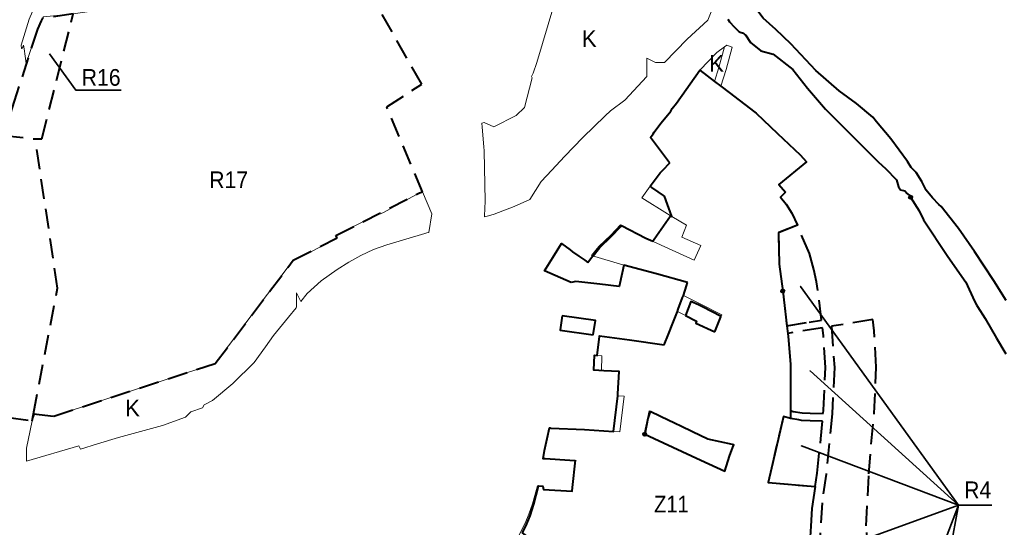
# Model space of a CAD drawing. Extents: x -650276 to -642489, y -1074311 to -1066658.
# Drawn here: x -646603 to -645192, y -1069923 to -1069193 of the extents above; entities that cross this region are included whole.
import ezdxf

# ---------------------------------------------------------------- set-up
doc = ezdxf.new("R2010")
doc.units = 0
doc.header["$LTSCALE"] = 9.6
doc.header["$PDMODE"] = 32
doc.header["$PDSIZE"] = 4.8
doc.linetypes.add('MEDIUM_DASHED', pattern=[4.5, 3, -1.5])
for name, color, linetype, lineweight in [('44', 7, 'Continuous', 40), ('45', 7, 'Continuous', 40), ('47', 7, 'Continuous', 13), ('48', 7, 'Continuous', 13), ('61', 7, 'MEDIUM_DASHED', 40), ('62', 7, 'Continuous', 35), ('63', 7, 'Continuous', 13)]:
    doc.layers.add(name, color=color, linetype=linetype, lineweight=lineweight)

msp = doc.modelspace()

# ---------------------------------------------------------------- linework, layer by layer
at = {"layer": '44'}
for points in [[(-645184.88, -1069596.58), (-645202.56, -1069568.23), (-645230.1, -1069525.98), (-645253.4, -1069493.06), (-645278.31, -1069461.33), (-645281.4, -1069458.4), (-645290.5, -1069449.03), (-645299.61, -1069437.97), (-645306.16, -1069425.55), (-645314.14, -1069412.54), (-645321.1, -1069405.21), (-645326.59, -1069396.64), (-645350.63, -1069363.98), (-645371.12, -1069339.47), (-645376.38, -1069332.65), (-645400.07, -1069313.32), (-645424.8, -1069295.24), (-645458.45, -1069265.56), (-645494.13, -1069227.63), (-645515.89, -1069206.66), (-645534.25, -1069190.56), (-645543.43, -1069178.39)], [(-645584.73, -1069191.88), (-645582.63, -1069195.88), (-645575.58, -1069203.57), (-645568.9, -1069209.87), (-645567.07, -1069210.45), (-645562.17, -1069212.02), (-645560.72, -1069214.25), (-645559.33, -1069214.54), (-645552.2, -1069225.59), (-645537.44, -1069237.41), (-645519.59, -1069242.38), (-645491.63, -1069264.25), (-645470.44, -1069291.24), (-645444.62, -1069321.35), (-645405.7, -1069360.27), (-645368.13, -1069397.37), (-645358.04, -1069406.84), (-645342.49, -1069423.06), (-645339.31, -1069433.27), (-645336.66, -1069437.47), (-645330.57, -1069438.89), (-645327.2, -1069442.53), (-645323.36, -1069445.79), (-645322.13, -1069447.96)], [(-645322.13, -1069447.96), (-645309.62, -1069467.79), (-645303.57, -1069480.49), (-645268.57, -1069533.23), (-645242.75, -1069570.26), (-645230.42, -1069597.39), (-645227.27, -1069602.68), (-645225.7, -1069605.32), (-645214.76, -1069622.37), (-645198.41, -1069650.49), (-645185.17, -1069673.38)]]:
    msp.add_lwpolyline(points, dxfattribs=at)
msp.add_point((-645322.13, -1069447.96), dxfattribs=at)
at = {"layer": '45'}
msp.add_line((-645704.355, -1069788.786), (-645623.75, -1069825.97), dxfattribs=at)
for points in [[(-645668.722, -1069398.75), (-645696.19, -1069362.01), (-645692.38, -1069356.67), (-645690.81, -1069354.28), (-645687.22, -1069349), (-645680.8, -1069341.08), (-645667, -1069324.06), (-645664.89, -1069320.2), (-645658.9, -1069312.83), (-645625.11, -1069265.42), (-645604.114, -1069281.49), (-645594.94, -1069288.511)], [(-645594.94, -1069288.511), (-645583.13, -1069297.55), (-645546.19, -1069325.81), (-645544.26, -1069327.35), (-645513.41, -1069356.18), (-645480.72, -1069386.96), (-645471.738, -1069397.026), (-645511.464, -1069429.794), (-645501.878, -1069440.838)], [(-645675.91, -1069446.56), (-645694.21, -1069433.78), (-645696.45, -1069432.21), (-645682.28, -1069412.88), (-645678.06, -1069408.54), (-645668.61, -1069398.9), (-645668.722, -1069398.75)], [(-645501.878, -1069440.838), (-645508.994, -1069447.955), (-645501, -1069458), (-645493, -1069471), (-645484.783, -1069488.256), (-645512, -1069499), (-645511, -1069544), (-645506, -1069583)], [(-645786.388, -1069541.673), (-645779.376, -1069532.962), (-645778.754, -1069532.198), (-645769.369, -1069520.672), (-645768.995, -1069520.305), (-645752.715, -1069504.328), (-645738.986, -1069489.868), (-645737.897, -1069488.534), (-645702.82, -1069506.64), (-645692.87, -1069511.229), (-645690.84, -1069508.32), (-645667.31, -1069474.6), (-645665.58, -1069475.61), (-645675.91, -1069446.56)], [(-645836.44, -1069534.5), (-645824.05, -1069514.34), (-645811.75, -1069523.81), (-645808.1, -1069526.61), (-645799.07, -1069532.8), (-645790.62, -1069538.59), (-645786.388, -1069541.673)], [(-645810.08, -1069570.39), (-645848.78, -1069553.91), (-645836.44, -1069534.5)], [(-645643.16, -1069570.6), (-645687.29, -1069558.04), (-645734.5, -1069545.89), (-645736.8, -1069556.91), (-645741.14, -1069576.19), (-645769.04, -1069573), (-645803.513, -1069569.263), (-645810.08, -1069570.39)], [(-645676.34, -1069660.28), (-645670.23, -1069644.67), (-645664.19, -1069629.24), (-645657.52, -1069612.2), (-645656.15, -1069608.71), (-645649.91, -1069592.39), (-645648.68, -1069589.06), (-645644.56, -1069575.61), (-645643.16, -1069570.6)], [(-645506, -1069583), (-645500.137, -1069632.833), (-645500.137, -1069632.833)], [(-645594.58, -1069619.56), (-645621.56, -1069605.68), (-645626.95, -1069602.91), (-645638.203, -1069597.8), (-645645.715, -1069618.085)], [(-645823.082, -1069618.279), (-645823.13, -1069618.452), (-645825.295, -1069632.053), (-645826.133, -1069638.843), (-645826.151, -1069639.057), (-645778.45, -1069645.92)], [(-645823.082, -1069618.279), (-645823.13, -1069618.452), (-645825.295, -1069632.053), (-645826.133, -1069638.843), (-645826.151, -1069639.057), (-645778.45, -1069645.92)], [(-645778.45, -1069645.92), (-645775.46, -1069625.13), (-645823.082, -1069618.279)], [(-645778.45, -1069645.92), (-645775.46, -1069625.13), (-645823.082, -1069618.279)], [(-645645.715, -1069618.085), (-645629.78, -1069626.03), (-645630.93, -1069628.84), (-645603.7, -1069641.75)], [(-645603.7, -1069641.75), (-645594.818, -1069620.139), (-645594.58, -1069619.56)], [(-645500.137, -1069632.833), (-645498, -1069648), (-645495, -1069688), (-645495, -1069744), (-645495, -1069766), (-645504.976, -1069763.332), (-645527, -1069858), (-645459.312, -1069864.01), (-645464.288, -1069895.362), (-645465.756, -1069921.035), (-645469.701, -1069990.011)], [(-645839.721, -1069780.247), (-645839.658, -1069779.835), (-645791.2, -1069781.92), (-645749.48, -1069784.61), (-645743.36, -1069733.7), (-645743.01, -1069730.72), (-645741.43, -1069698.68), (-645763.24, -1069697.58), (-645777.62, -1069696.85), (-645776.45, -1069675.26), (-645773.02, -1069675.47), (-645769.36, -1069648), (-645769.264, -1069647.213), (-645726.57, -1069653.22), (-645676.34, -1069660.28)], [(-645696.517, -1069756.039), (-645700.028, -1069766.286), (-645704.355, -1069788.786)], [(-645660.57, -1069773.31), (-645681.76, -1069763.13), (-645696.517, -1069756.039)], [(-645804.185, -1069825.84), (-645804.28, -1069826.76), (-645812.18, -1069826.3), (-645847.62, -1069824.26), (-645850.63, -1069824.09), (-645848.35, -1069812.09), (-645844.57, -1069795.07), (-645841.41, -1069779.76), (-645839.658, -1069779.835), (-645839.721, -1069780.247)], [(-645613.84, -1069795.78), (-645635.79, -1069785.23), (-645652.378, -1069777.251), (-645660.57, -1069773.31)], [(-645623.75, -1069825.97), (-645589.23, -1069841.89), (-645582.31, -1069820.05), (-645577.52, -1069807.26), (-645576.34, -1069804.13), (-645578.134, -1069803.731), (-645613.84, -1069795.78)], [(-645742.967, -1069941.862), (-645768.424, -1069948.431), (-645833, -1069966), (-645880.431, -1069930.3), (-645874.219, -1069917.496), (-645869.262, -1069905.935), (-645863.95, -1069889.468), (-645857.289, -1069863.338), (-645857.204, -1069862.954), (-645850.92, -1069863.41), (-645849.79, -1069868.4), (-645808.84, -1069870.75), (-645808.28, -1069865.39), (-645804.185, -1069825.84)]]:
    msp.add_lwpolyline(points, dxfattribs=at)
for p in [(-645506, -1069583), (-645704.355, -1069788.786)]:
    msp.add_point(p, dxfattribs=at)
at = {"layer": '47'}
for points in [[(-646593.793, -1069255.911), (-646577.878, -1069206.485), (-646572.586, -1069194.485), (-646569.114, -1069188.86), (-646526.31, -1069184.381), (-646479.84, -1069177.626), (-646250.409, -1069137.52), (-646153.307, -1069059.947), (-646161.484, -1069046.228), (-646256.824, -1069123.414)], [(-646547.412, -1069071.71), (-646549.91, -1069072.542), (-646564.54, -1069125.08), (-646564.605, -1069125.271), (-646574.978, -1069163.017), (-646574.978, -1069163.017), (-646574.33, -1069162.04), (-646575.87, -1069164.54), (-646581.29, -1069173.32), (-646589.56, -1069192.07), (-646601.41, -1069229.34)], [(-645835.157, -1069172.184), (-645859.43, -1069254.08), (-645864.96, -1069269.78), (-645867.42, -1069274.21), (-645866.45, -1069276.32), (-645877.15, -1069319.06), (-645877.15, -1069319.06), (-645889.29, -1069330.52), (-645921.56, -1069346.6), (-645935.33, -1069340.64), (-645938.89, -1069341.56), (-645938.399, -1069347.452)], [(-645938.399, -1069347.452), (-645936.046, -1069375.651), (-645935.58, -1069381.24), (-645933.97, -1069453.52), (-645934.8, -1069474.71), (-645935.05, -1069476.32), (-645928.99, -1069474.55), (-645921.13, -1069472.25), (-645892.03, -1069461.43), (-645869.91, -1069451.02), (-645853.28, -1069425.27), (-645838.17, -1069409.28), (-645819.62, -1069389.66), (-645793.63, -1069362.15), (-645761.411, -1069331.17), (-645753.58, -1069323.64), (-645733.1, -1069308.58), (-645701.62, -1069274.36), (-645701.33, -1069247.86), (-645689, -1069254.5), (-645675.82, -1069254.48), (-645643.34, -1069220.59), (-645613.9, -1069193.45), (-645608.71, -1069181.51)], [(-646601.41, -1069229.34), (-646600.68, -1069234.21), (-646599.79, -1069234.07), (-646597.77, -1069229.37), (-646596.95, -1069234.83), (-646593.793, -1069255.911)], [(-645604.114, -1069281.49), (-645597.738, -1069261.522), (-645589.844, -1069231.908), (-645600.55, -1069239.93), (-645625.11, -1069265.42)], [(-645625.11, -1069265.42), (-645625.11, -1069265.42), (-645604.114, -1069281.49)], [(-646023.96, -1069440.34), (-646028.16, -1069441.58), (-646080.35, -1069469.89), (-646102.15, -1069479.49), (-646148.5, -1069503), (-646146.8, -1069506.6), (-646189.17, -1069528.74), (-646209.9, -1069538.5), (-646321.973, -1069686.855), (-646554.262, -1069762.602), (-646581.489, -1069759.421), (-646585.51, -1069769.57)], [(-646017.63, -1069499.08), (-646017.63, -1069499.08), (-646015.16, -1069498.74), (-646010.65, -1069471.91), (-646023.96, -1069440.34)], [(-646491.18, -1069802.78), (-646491.18, -1069802.78), (-646460.97, -1069793.56), (-646397.74, -1069776.29), (-646364.67, -1069764.23), (-646357, -1069756.7), (-646340.48, -1069750.92), (-646337.97, -1069746.4), (-646325.92, -1069740.05), (-646296.64, -1069715.72), (-646266.27, -1069685.75), (-646250, -1069663.09), (-646238.19, -1069646.63), (-646212.43, -1069615.33), (-646210.03, -1069612.42), (-646205.9, -1069607.17), (-646205, -1069606.03), (-646205.25, -1069585.67), (-646198.82, -1069597.83), (-646190.07, -1069586.48), (-646169.9, -1069568.04), (-646146.81, -1069551.97), (-646129.87, -1069541.19), (-646112.56, -1069531.78), (-646094.39, -1069523.34), (-646075.48, -1069516.38), (-646020.75, -1069500), (-646017.63, -1069499.08)], [(-646585.51, -1069769.57), (-646588.25, -1069783.37), (-646593.34, -1069808.99), (-646593.34, -1069827.68)], [(-646593.34, -1069827.68), (-646518.19, -1069805.27), (-646515.63, -1069810.24), (-646491.18, -1069802.78)]]:
    msp.add_lwpolyline(points, dxfattribs=at)
at = {"layer": '61'}
for points in [[(-646583.457, -1069759.191), (-646554.262, -1069762.602), (-646321.973, -1069686.855), (-646209.9, -1069538.5), (-646146.8, -1069506.6), (-646148.5, -1069503), (-646028.16, -1069441.58), (-646023.96, -1069440.34), (-646075.49, -1069318.19), (-646025.14, -1069285.394), (-646153.307, -1069059.947)], [(-646642.89, -1069357.68), (-646652.72, -1069388.08), (-646677.18, -1069463.79), (-646693.58, -1069550.28), (-646698.4, -1069578.93), (-646697.31, -1069579.97), (-646697.31, -1069583.47), (-646666.36, -1069588.57), (-646659.83, -1069601.8), (-646659.52, -1069605.53), (-646662.57, -1069621.66), (-646671.69, -1069669.92), (-646678.52, -1069705.63), (-646680.28, -1069714.83), (-646677.36, -1069733.65), (-646679.46, -1069745.37), (-646622, -1069759.34), (-646619.49, -1069764.46), (-646585.51, -1069769.57), (-646583.457, -1069759.191), (-646548.91, -1069578.56), (-646580.797, -1069364.111)]]:
    msp.add_lwpolyline(points, dxfattribs=at)
for points in [[(-646572.586, -1069194.485), (-646577.878, -1069206.485), (-646611.107, -1069309.68), (-646626.774, -1069359.349), (-646580.797, -1069364.111), (-646571.479, -1069363.822), (-646526.31, -1069184.381), (-646570.296, -1069190.776)], [(-645506, -1069583), (-645500.137, -1069632.833), (-645468, -1069627.622), (-645450.05, -1069624.711), (-645457.223, -1069569.632), (-645461.32, -1069552.039), (-645467.477, -1069528.79), (-645484.783, -1069488.256), (-645512, -1069499), (-645511, -1069544)], [(-645374.642, -1069640.059), (-645376.605, -1069623.944), (-645435.877, -1069633.555), (-645431.642, -1069692.811), (-645434.826, -1069759.235), (-645443.679, -1069846.142), (-645449.445, -1069887.328), (-645455.84, -1069992.731), (-645379.881, -1070001.766), (-645385.95, -1069920.347), (-645382.14, -1069845.883), (-645378.587, -1069802.788), (-645374.542, -1069758.923), (-645371.563, -1069692.39)], [(-645495, -1069688), (-645495, -1069744), (-645495, -1069754.815), (-645491, -1069756), (-645478, -1069758), (-645466.517, -1069758.328), (-645447.852, -1069758.862), (-645447.398, -1069753.935), (-645444.664, -1069692.902), (-645447.387, -1069646.623), (-645448.725, -1069635.639), (-645498.61, -1069643.729), (-645498, -1069648)], [(-645504.976, -1069763.332), (-645527, -1069858), (-645464.93, -1069863.477), (-645459.312, -1069864.01), (-645456.586, -1069844.534), (-645451.227, -1069795.473), (-645448.864, -1069769.837), (-645466.353, -1069769.337), (-645478.997, -1069768.976), (-645482.753, -1069768.26), (-645495, -1069766)]]:
    msp.add_lwpolyline(points, close=True, dxfattribs=at)
at = {"layer": '62'}
msp.add_line((-645253.165, -1069890.903), (-645338.143, -1070356.741), dxfattribs=at)
for points in [[(-646457.55, -1069294.294), (-646522.377, -1069294.294), (-646560.609, -1069241.94)], [(-645205.454, -1069890.903), (-645253.165, -1069890.903), (-645480.406, -1069576.285), (-645253.165, -1069890.903), (-645466.774, -1069697.69), (-645253.165, -1069890.903), (-645479.043, -1069805.455), (-645253.165, -1069890.903), (-645420.426, -1069951.415), (-645253.165, -1069890.903), (-645348.178, -1070139.662)]]:
    msp.add_lwpolyline(points, dxfattribs=at)
at = {"layer": '62', "lineweight": 13}
msp.add_lwpolyline([(-646457.55, -1069294.294), (-646522.377, -1069294.294), (-646560.609, -1069241.94)], dxfattribs=at)
at = {"layer": '63'}
for points in [[(-645469.701, -1069990.011), (-645465.756, -1069921.035), (-645464.898, -1069906.036), (-645464.288, -1069895.362), (-645462.303, -1069885.376), (-645459.312, -1069864.01), (-645527, -1069858), (-645504.976, -1069763.332), (-645495, -1069766), (-645495, -1069754.815), (-645495, -1069744), (-645495, -1069688), (-645498.61, -1069643.729), (-645500.137, -1069632.833), (-645506, -1069583), (-645511, -1069544), (-645512, -1069499), (-645484.783, -1069488.256), (-645493, -1069471), (-645501, -1069458), (-645508.994, -1069447.955), (-645502.142, -1069441.313), (-645511.464, -1069429.794), (-645471.738, -1069397.026), (-645480.72, -1069386.96), (-645513.41, -1069356.18), (-645546.19, -1069325.81), (-645583.13, -1069297.55), (-645594.94, -1069288.511), (-645587.298, -1069264.578), (-645578.713, -1069232.375), (-645586.39, -1069229.32), (-645589.844, -1069231.908), (-645600.55, -1069239.93), (-645625.11, -1069265.42), (-645658.9, -1069312.83), (-645664.89, -1069320.2), (-645667, -1069324.06), (-645692.38, -1069356.67), (-645696.19, -1069362.01)], [(-645696.19, -1069362.01), (-645696.19, -1069362.01), (-645668.61, -1069398.9), (-645678.06, -1069408.54), (-645682.28, -1069412.88), (-645696.45, -1069432.21), (-645708.48, -1069448.63), (-645671.75, -1069471.99), (-645667.31, -1069474.6), (-645665.58, -1069475.61), (-645644.18, -1069488.17), (-645651.26, -1069505.47), (-645623.545, -1069517.563), (-645633.29, -1069538.7), (-645659.84, -1069526.46), (-645702.82, -1069506.64), (-645739.3, -1069487.81), (-645753.05, -1069502.47), (-645770.66, -1069519.07), (-645780.85, -1069531.55), (-645734.5, -1069545.89), (-645643.16, -1069570.6), (-645644.56, -1069575.61)], [(-645644.56, -1069575.61), (-645644.56, -1069575.61), (-645648.68, -1069589.06), (-645625.81, -1069600.63), (-645593.609, -1069617.075), (-645594.58, -1069619.56), (-645603.7, -1069641.75), (-645630.93, -1069628.84), (-645629.78, -1069626.03), (-645657.52, -1069612.2), (-645664.19, -1069629.24), (-645670.23, -1069644.67), (-645676.34, -1069660.28), (-645726.57, -1069653.22), (-645769.298, -1069647.215), (-645769.36, -1069648), (-645773.02, -1069675.47), (-645766.017, -1069675.979), (-645766.701, -1069697.419), (-645741.43, -1069698.68), (-645743.01, -1069730.72), (-645743.36, -1069733.7), (-645733.972, -1069734.1), (-645740.394, -1069785.402), (-645749.48, -1069784.61), (-645791.2, -1069781.92), (-645841.41, -1069779.76), (-645844.57, -1069795.07), (-645848.35, -1069812.09), (-645850.63, -1069824.09), (-645847.62, -1069824.26), (-645812.18, -1069826.3), (-645804.28, -1069826.76), (-645804.38, -1069830.61), (-645806.07, -1069844.09), (-645808.28, -1069865.39), (-645808.84, -1069870.75), (-645849.79, -1069868.4), (-645850.92, -1069863.41), (-645858.78, -1069862.84), (-645865.78, -1069888.76), (-645870.89, -1069903.5), (-645876.15, -1069916.47)], [(-645647.25, -1069815.13), (-645623.75, -1069825.97), (-645589.23, -1069841.89), (-645582.31, -1069820.05), (-645577.52, -1069807.26), (-645576.34, -1069804.13), (-645613.84, -1069795.78), (-645635.79, -1069785.23), (-645660.57, -1069773.31), (-645681.76, -1069763.13), (-645698.16, -1069755.25), (-645705.3, -1069788.35)], [(-645705.3, -1069788.35), (-645647.25, -1069815.13), (-645647.25, -1069815.13)], [(-645876.15, -1069916.47), (-645892.09, -1069947.98)]]:
    msp.add_lwpolyline(points, dxfattribs=at)

# ---------------------------------------------------------------- texts
at = {"layer": '45', "width": 0.9}
msp.add_text('Z11', height=24, dxfattribs=at).set_placement((-645690.933, -1069901.172))
at = {"layer": '48'}
for p in [(-645795.003, -1069231.861), (-645795.003, -1069231.861), (-645611.977, -1069267.447), (-646451.743, -1069763.13), (-646451.743, -1069763.13)]:
    msp.add_text('K', height=24, dxfattribs=at).set_placement(p)
at = {"layer": '62', "width": 0.95}
for s, p in [('R16', (-646514.063, -1069287.733)), ('R17', (-646330.736, -1069434.917)), ('R4', (-645245.139, -1069880.683))]:
    msp.add_text(s, height=24, dxfattribs=at).set_placement(p)

doc.saveas('drawing.dxf')
